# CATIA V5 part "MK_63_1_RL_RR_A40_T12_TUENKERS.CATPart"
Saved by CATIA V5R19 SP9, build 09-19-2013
Part number: MK_63_1_RL_RR_A40_T12_TUENKERS
Material "MISCHDICHTE": density 4951.5 kg/m3, Young's modulus 2e+11 Pa, Poisson ratio 0.266
Bounding box of the stored display mesh (mm): x -193.5 to 132.266, y -121.5 to 144, z -122.161 to 122.161
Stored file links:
  G:\Konstruktion\Modelle\Catia_V5\MK_63_1_RL_RR_A40_T12_TUENKERS.CATPart
  G:\Konstruktion\Modelle\Catia_V5\Spannarme\SPANNARM_KPL_63_A10_217498_TUENKERS.CATPart
  C:\Catia\Tuenkers_B19SP9HF86_64\win_b64\reffiles\standard\MetricThickPitch.txt
  G:\Konstruktion\Modelle\Catia_V5\Spannarme\SPANNARM_KPL_63_A40_242839_TUENKERS.CATPart
  G:\Konstruktion\Modelle\Catia_V5\MK_63_1_A10_T12_TUENKERS.CATPart
  G:\Konstruktion\Modelle\Catia_V5\MK2_63_1_A40_T12_TUENKERS.CATPart
  G:\Konstruktion\Modelle\Catia_V5\V2_63_1_BR3_ZL_ZR_RL_RR_A40_T12_TUENKERS.CATPart
  HANDHEBEL_KPL_50_63_TUENKERS.CATPart
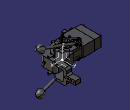
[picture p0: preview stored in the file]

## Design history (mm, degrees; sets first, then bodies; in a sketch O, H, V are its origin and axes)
AxisSystem1: origin (0, 0, 0), X (1, 0, 0), Y (0, 1, 0), Z (0, 0, 1)
Body1 (main body)
  Body2 "*DIT1\\*DIT2\\"
    Solid1: solid without history
  Assemble1: tool Body2
  Body3 "*DIT1\\*DIT3"
    Solid2 "Solid.1": solid without history
  Assemble2: tool Body3
  Body4 "*DIT1\\*DIT12\\*DIT16\\"
    Solid3 "Solid.1": solid without history
  Assemble3: tool Body4
  Body5 "*DIT1\\*DIT12\\*DIT17\\"
    Solid4 "Solid.1": solid without history
  Assemble4: tool Body5
  Body6 "*DIT1\\*DIT12\\MK_MK2_63_1_A10_A11_A12_T12_081112_3D_xSET4_2.1"
    Solid5 "Solid.1": solid without history
    Body7 "*DIT1\\*DIT12\\MK_MK2_63_1_A10_A11_A12_T12_081112_3D_xSET4_2.1\\Body.11 ( *SOL16 - wsp GEHAEUSE -  )"
      Solid6 "Solid.1": solid without history
    Add1 "*DIT1\\*DIT12\\MK_MK2_63_1_A10_A11_A12_T12_081112_3D_xSET4_2.1\\Body.11 ( *SOL16 - wsp GEHAEUSE -  )": tool Body7
    Body8 "*DIT1\\*DIT12\\MK_MK2_63_1_A10_A11_A12_T12_081112_3D_xSET4_2.1\\Body.12 ( *SOL17 - wsp GEHAEUSE -  )"
      Solid7 "Solid.1": solid without history
    Add2 "*DIT1\\*DIT12\\MK_MK2_63_1_A10_A11_A12_T12_081112_3D_xSET4_2.1\\Body.12 ( *SOL17 - wsp GEHAEUSE -  )": tool Body8
    Body9 "*DIT1\\*DIT12\\MK_MK2_63_1_A10_A11_A12_T12_081112_3D_xSET4_2.1\\Body.14 ( *SOL18 - wsp GEHAEUSE -  )"
      Solid8 "Solid.1": solid without history
    Add3 "*DIT1\\*DIT12\\MK_MK2_63_1_A10_A11_A12_T12_081112_3D_xSET4_2.1\\Body.14 ( *SOL18 - wsp GEHAEUSE -  )": tool Body9
  Assemble5: tool Body6
  Body10 "*DIT1\\MK_MK2_63_1_A10_A11_A12_T12_081112_3D_xSET2_1.1"
    Solid9 "Solid.1": solid without history
  Assemble6: tool Body10
  Rotate1: Axis edge [XY plane of AxisSystem1 | ZX plane of AxisSystem1], Angle 90, ToTransfor Assemble6
  Body11
    Body12 "*DIT1\\MK_MK2_63_1_A10_A11_A12_T12_081112_3D_xSET2_1.1\\Body.2 ( *SOL2 - wsp MK_MK2 63_1 -  )"
      Solid10 "Solid.1": solid without history
    Assemble7: tool Body12
    Body13 "*DIT1\\MK_MK2_63_1_A10_A11_A12_T12_081112_3D_xSET2_1.1\\Body.3 ( *SOL3 - wsp MK_MK2 63_1 -  )"
      Solid11 "Solid.1": solid without history
    Assemble8: tool Body13
    Body14 "*DIT1\\MK_MK2_63_1_A10_A11_A12_T12_081112_3D_xSET2_1.1\\Body.4 ( *SOL4 - wsp MK_MK2 63_1 -  )"
      Solid12 "Solid.1": solid without history
    Assemble9: tool Body14
    Body15 "*DIT1\\MK_MK2_63_1_A10_A11_A12_T12_081112_3D_xSET2_1.1\\Body.5 ( *SOL5 - wsp MK_MK2 63_1 -  )"
      Solid13 "Solid.1": solid without history
    Assemble10: tool Body15
    Body16 "*DIT1\\MK_MK2_63_1_A10_A11_A12_T12_081112_3D_xSET2_1.1\\Body.6 ( *SOL6 - wsp MK_MK2 63_1 -  )"
      Solid14 "Solid.1": solid without history
    Assemble11: tool Body16
    Rotate2: Axis edge, Angle 90, ToTransfor Assemble11
    Translate1: Direction edge [YZ plane of AxisSystem1 | XY plane of AxisSystem1], Length -1, ToTransfor Rotate2
  Assemble12: tool Body11
Body17 "Spannarm_kpl_63_A40_242839_Tuenkers", material "Steel"
  Sketch1 on xy-plane, origin (0, 0, 0), H (1, 0, 0), V (0, 1, 0)
    line L1 (73, 144) -> (45, 144)
    arc A1 centre (53, 43.1005) radius 20 from (67.1421, 28.9584) to (73, 43.1005) ccw
    line L2 (67.1421, 28.9584) -> (19.0919, -19.0919)
    line L3 (10.9602, 10.9602) -> (10.9602, -10.9602)
    line L4 (10.9602, 10.9602) -> (-10.9602, 10.9602)
    line L5 (-19.0919, 19.0919) -> (-10.9602, 10.9602)
    line L6 (-1.4396, 36.7442) -> (-19.0919, 19.0919)
    line L7 (38.4202, 51.252) -> (-1.4396, 36.7442)
    arc A2 centre (35, 60.6489) radius 10 from (38.4202, 51.252) to (45, 60.6489) ccw
    line L8 (45, 60.6489) -> (45, 144)
    line L9 (73, 144) -> (73, 43.1005)
    line L10 (10.9602, -10.9602) -> (19.0919, -19.0919)
    point P7 (10.9602, 10.9602)
    point P10 (-1.4396, 36.7442)
    point P13 (73, 37.6447)
    point P14 (45, 51.7188)
    reference intersected line E1 through (0, 0) direction (-0.7071, 0.7071)
    reference intersected line E2 through (0, 0) direction (-0.7071, 0.7071)
    reference intersected line E3 through (0, 0) direction (-0.7071, 0.7071)
    reference intersected line E4 through (0, 0) direction (0, 1) from yz-plane
    reference intersected line E5 through (0, 0) direction (-1, 0) from zx-plane
    reference intersected line E6 through (0, 0) direction (0, 1) from yz-plane
    angle L6 L7 = 25
    radius A1 = 20
    angle L4 L5 = 45
    distance P7 L2 = 27
    distance L2 L6 = 54
    angle L2 L10 = 90
    distance P7 E1 = 15.5
    distance E4 L3 = 10.9602
    distance E5 L1 = 144
    distance E6 L8 = 45
    distance L9 L8 = 28
    radius A2 = 10
    distance P10 L1 = 107.2558
    tangency: A1 L2, L8 A2, A2 L7, L9 A1
    coincidence: L10 E2, L5 E3
  Pad1: profile Sketch1, direction (0, 0, 1), length 39, opposite side length 39
  Chamfer1: length 0.1, angle 45, on edge [face of Pad1 from Sketch1.L3 | end face of Pad1]; edge [face of Pad1 from Sketch1.L4 | end face of Pad1]; edge [start face of Pad1 | face of Pad1 from Sketch1.L4]; edge [start face of Pad1 | face of Pad1 from Sketch1.L3]
  Sketch2 on face of Pad1 from Sketch1.L9, origin (73, 0, 0), H (0, 1, 0), V (0, 0, 1)
    line L1 (144, -10) -> (144, 10)
    line L2 (103, 10) -> (144, 10)
    arc A1 centre (103, 18) radius 8 from (103, 10) to (95, 18) cw
    line L3 (95, 18) -> (95, 29)
    arc A2 centre (85, 29) radius 10 from (85, 39) to (95, 29) cw
    line L4 (-20, 39) -> (85, 39)
    line L5 (-20, 39) -> (-20, 27)
    line L6 (74, 27) -> (-20, 27)
    arc A3 centre (74, 21) radius 6 from (74, 27) to (80, 21) cw
    line L7 (80, 21) -> (80, -21)
    arc A4 centre (74, -21) radius 6 from (80, -21) to (74, -27) cw
    line L8 (-20, -27) -> (74, -27)
    line L9 (-20, -27) -> (-20, -39)
    line L10 (-20, -39) -> (85, -39)
    arc A5 centre (85, -29) radius 10 from (95, -29) to (85, -39) cw
    line L11 (95, -29) -> (95, -18)
    arc A6 centre (103, -18) radius 8 from (95, -18) to (103, -10) cw
    line L12 (103, -10) -> (144, -10)
    reference intersected line E1 through (0, 0) direction (-1, 0) from xy-plane
    reference intersected line E2 through (0, 0) direction (0, 1) from zx-plane
    reference intersected line E3 through (0, 0) direction (0, 1) from zx-plane
    reference intersected line E4 through (0, 0) direction (0, 1) from zx-plane
    line L13 (-30, -44) -> (160, -44)
    line L14 (160, -44) -> (160, 44)
    line L15 (160, 44) -> (-30, 44)
    line L16 (-30, 44) -> (-30, -44)
    reference intersected line E5 through (0, 0) direction (-1, 0) from xy-plane
    reference intersected line E6 through (0, 0) direction (0, 1) from zx-plane
    distance L12 E1 = 10
    distance L12 L2 = 20
    distance L4 L10 = 78
    distance L6 L8 = 54
    distance L10 L12 = 29
    distance L8 L10 = 12
    radius A3 = 6
    radius A4 = 6
    radius A5 = 10
    radius A2 = 10
    radius A1 = 8
    radius A6 = 8
    distance L7 E2 = 80
    distance L3 E3 = 95
    distance L1 L5 = 164
    distance E4 L1 = 144
    distance L16 L14 = 190
    distance L15 L13 = 88
    distance L13 E5 = 44
    distance L14 E6 = 160
    tangency: L6 A3, A3 L7, L7 A4, A4 L8, L10 A5, A5 L11, L3 A1, A1 L2, A6 L12, A2 L4, A2 L3, A6 L11
    vertical: L1 V, L14 V, L16 V
    horizontal: L12 H, L13 H, L15 H
    coincidence: L5 L9, L11 L3
  Pocket1: profile Sketch2, direction (-1, 0, 0), length 95
  Sketch3 on face of Pad1 from Sketch1.L9, origin (73, 131.0889, -0.3784), H (0, 1, 0), V (0, 0, 1)
    point P1 (3.9111, 0.3784)
    reference intersected line E1 through (0, 0.3784) direction (-1, 0) from xy-plane
    reference intersected line E2 through (-131.0889, 0) direction (0, 1) from zx-plane
    reference intersected line E3 through (-131.0889, 0) direction (0, 1) from zx-plane
    reference intersected line E4 (12.9111, -38.6216) -> (-87.9884, -38.6216) from start face of Pad1
    distance P1 E2 = 135
    distance E3 E4 = 0
    coincidence: P1 E1
  Hole1: placed by Sketch3, at (73, 135, 0) direction (-1, 0, 0), diameter 6, through (limit type 6)
  Sketch4 on face of Pad1 from Sketch1.L9, origin (73, 113.9529, 0.5693), H (0, 1, 0), V (0, 0, 1)
    point P1 (-8.9529, -0.5693)
    reference projected point E1 (21.0471, -0.5693) from axis of face of Hole1
    reference intersected line E2 through (0, -0.5693) direction (-1, 0) from xy-plane
    distance P1 E1 = 30
    coincidence: P1 E2
  Hole2: placed by Sketch4, at (73, 105, 0) direction (-1, 0, 0), diameter 6, through (limit type 6)
  Sketch5 on face of Pad1 from Sketch1.L9, origin (73, 123.4122, -0.1089), H (0, 1, 0), V (0, 0, 1)
    point P1 (-3.4122, 0.1089)
    reference projected point E1 (11.5878, 0.1089) from axis of face of Hole1
    reference projected point E2 (-18.4122, 0.1089) from axis of face of Hole2
    distance P1 E1 = 15
    distance E2 P1 = 15
  Hole3: placed by Sketch5, at (73, 120, 0) direction (-1, 0, 0), diameter 9, through (limit type 6)
  Sketch6 on face of Pad1 from Sketch1.L9, origin (73, 93.5248, 1.4062), H (0, 1, 0), V (0, 0, 1)
    point P1 (-3.5248, -1.4062)
    reference projected point E1 (26.4752, -1.4062) from axis of face of Hole3
    reference projected point E2 (11.4752, -1.4062) from axis of face of Hole2
    distance P1 E1 = 30
    distance P1 E2 = 15
  Hole4: placed by Sketch6, at (73, 90, 0) direction (-1, 0, 0), diameter 9, through (limit type 6)
  Sketch7 on face of Pad1 from Sketch1.L10, origin (13.7879, -13.7879, 28.7565), H (0.7071, -0.7071, 0), V (0, 0, 1)
    point P1 (0.5009, 4.2435)
    reference intersected line E1 through (0, -28.7565) direction (-1, 0) from xy-plane
    reference projected line E2 (-19.4991, -67.7565) -> (-19.4991, 10.2435) from edge [face of Pad1 from Sketch1.L3 | face of Pad1 from Sketch1.L4]
    distance P1 E1 = 33
    distance E2 P1 = 20
  Hole5: placed by Sketch7, at (14.1421, -14.1421, 33) direction (0.7071, 0.7071, 0), diameter 6.647, depth 18, V-bottom angle 120, threaded "M8", thread diameter 8, thread depth 15, pitch 1.25
  RectPattern1: of Hole5, direction 1 instances 2, spacing 66, along edge [face of Pad1 from Sketch1.L3 | face of Pad1 from Sketch1.L4] reversed, direction 2 instances 2, spacing 40, along edge [face of Pad1 from Sketch1.L10 | face of Pocket1] reversed
  Body18 "KLEMMFLANSCH KPL"
    Sketch8 on xy-plane, origin (0, 0, 0), H (1, 0, 0), V (0, 1, 0)
      line L1 (-20.5061, 17.6777) -> (-31.1375, 7.0463)
      line L2 (-31.1375, 7.0463) -> (-19.1167, -4.9745)
      line L3 (-19.1167, -4.9745) -> (-25.4806, -11.3385)
      line L4 (-25.4806, -11.3385) -> (-11.3385, -25.4806)
      line L5 (-11.3385, -25.4806) -> (-4.9745, -19.1167)
      line L6 (-4.9745, -19.1167) -> (7.0463, -31.1375)
      line L7 (7.0463, -31.1375) -> (19.0671, -19.1167)
      line L8 (19.0671, -19.1167) -> (10.9106, -10.9602)
      line L9 (10.9106, -10.9602) -> (-10.9602, -10.9602)
      point P10 (-10.9602, -10.9602)
      line L10 (-10.9602, -10.9602) -> (-10.9602, 8.1317)
      line L11 (-10.9602, 8.1317) -> (-20.5061, 17.6777)
      reference intersected line E1 through (0, 0) direction (-0.7071, 0.7071)
      reference intersected line E2 through (0, 0) direction (-0.7071, 0.7071)
      reference intersected line E3 through (0, 0) direction (-0.7071, -0.7071)
      distance L4 L8 = 26
      distance L7 L5 = 17
      distance L5 L3 = 20
      distance L7 L1 = 54
      distance L4 L6 = 9
      distance E1 P10 = 15.5
      distance L11 E2 = 2
      distance L11 L8 = 1.965
      angle L11 L10 = 135
      angle L9 L8 = 45
      distance L7 P10 = 27
      distance E3 L7 = 27
      coincidence: L2 L6
    Pad2: profile Sketch8, direction (0, 0, 1), length 39, opposite side length -27
    Chamfer2: length 0.1, angle 45, on edge [face of Pad2 from Sketch8.L9 | end face of Pad2]; edge [face of Pad2 from Sketch8.L10 | end face of Pad2]
    Sketch9 on face of Pad2 from Sketch8.L6, origin (-12.0456, -12.0456, 0), H (0.7071, -0.7071, 0), V (0, 0, 1)
      circle A1 centre (20, 33) radius 4
      point P1 (20, 33)
      circle A2 centre (-20, 33) radius 4
      point P2 (-20, 33)
      reference projected line E1 (-27, 27) -> (-10, 27) from edge [start face of Pad2 | face of Pad2 from Sketch8.L2]
      reference projected line E2 (10, 27) -> (27, 27) from edge [start face of Pad2 | face of Pad2 from Sketch8.L6]
      reference projected line E3 (27, 27) -> (27, 39) from edge [face of Pad2 from Sketch8.L7 | face of Pad2 from Sketch8.L6]
      reference projected line E4 (-27, 27) -> (-27, 39) from edge [face of Pad2 from Sketch8.L2 | face of Pad2 from Sketch8.L1]
      radius A1 = 4
      radius A2 = 4
      distance E1 P2 = 6
      distance P1 E2 = 6
      distance E3 P1 = 7
      distance P2 E4 = 7
    Pad3: profile Sketch9, direction (0.7071, 0.7071, 0), length 20
    Sketch10 on face of Pad3, origin (-12.0456, -12.0456, 0), H (0.7071, -0.7071, 0), V (0, 0, 1)
      circle A1 centre (20, 33) radius 6.5
      point P1 (20, 33)
      circle A2 centre (-20, 33) radius 6.5
      point P2 (-20, 33)
      reference projected line E1 (-27, 27) -> (-27, 39) from edge [face of Pad2 from Sketch8.L2 | face of Pad2 from Sketch8.L1]
      reference projected line E2 (27, 27) -> (27, 39) from edge [face of Pad2 from Sketch8.L7 | face of Pad2 from Sketch8.L6]
      reference projected line E3 (-27, 27) -> (-10, 27) from edge [start face of Pad2 | face of Pad2 from Sketch8.L2]
      reference projected line E4 (10, 27) -> (27, 27) from edge [start face of Pad2 | face of Pad2 from Sketch8.L6]
      radius A1 = 6.5
      radius A2 = 6.5
      distance E1 P2 = 7
      distance E2 P1 = 7
      distance E3 P2 = 6
      distance E4 P1 = 6
    Pad4: profile Sketch10, direction (-0.7071, -0.7071, 0), length 1.4
    Chamfer3: length 0.1, angle 45, on edge [face of Pad4 from Sketch10.A1 | end face of Pad4]; edge [face of Pad4 from Sketch10.A2 | end face of Pad4]
    Sketch11 on end face of Pad4, origin (-13.0355, -13.0355, 0), H (0.7071, -0.7071, 0), V (0, 0, 1)
      circle A1 centre (20, 33) radius 6.5
      point P1 (20, 33)
      circle A2 centre (-20, 33) radius 6.5
      point P2 (-20, 33)
      reference projected line E1 (10, 27) -> (27, 27) from edge [start face of Pad2 | face of Pad3]
      reference projected line E2 (27, 27) -> (27, 39) from edge [face of Pad2 from Sketch8.L7 | face of Pad2 from Sketch8.L6]
      reference projected line E3 (-27, 27) -> (-27, 39) from edge [face of Pad2 from Sketch8.L2 | face of Pad2 from Sketch8.L1]
      reference projected line E4 (-27, 27) -> (-10, 27) from edge [start face of Pad2 | face of Pad3]
      radius A1 = 6.5
      radius A2 = 6.5
      distance E1 P1 = 6
      distance E2 P1 = 7
      distance E3 P2 = 7
      distance E4 P2 = 6
    Pad5: profile Sketch11, direction (-0.7071, -0.7071, 0), length 8
    Fillet1: radius 0.5, on end face of Pad5; edge [face of Pad5 from Sketch11.A1 | end face of Pad5]
    Mirror1: of the body so far, about xy-plane, deactivated
  Assemble13: tool Body18
Body19 "ENDLAGENRASTE_RECHTS"
  Body20 "LUMP69"
    Solid15 "Manifold Solid #2521": solid without history
  Assemble14: tool Body20
  Body21 "LUMP71"
    Solid16 "Manifold Solid #3035": solid without history
  Assemble15: tool Body21
  Body22 "LUMP72"
    Solid17 "Manifold Solid #3745": solid without history
  Assemble16: tool Body22
  Body23 "LUMP75"
    Solid18 "Manifold Solid #6741": solid without history
  Assemble17: tool Body23
  Body24 "LUMP77"
    Solid19 "Manifold Solid #7511": solid without history
  Assemble18: tool Body24
  Body25 "LUMP78"
    Solid20 "Manifold Solid #7920": solid without history
  Assemble19: tool Body25
  Body26 "LUMP80"
    Solid21 "Manifold Solid #8586": solid without history
  Assemble20: tool Body26
  Body27 "LUMP83"
    Solid22 "Manifold Solid #9661": solid without history
  Assemble21: tool Body27
  Body28 "LUMP84"
    Solid23 "Manifold Solid #9918": solid without history
  Assemble22: tool Body28
  Body29 "LUMP86"
    Solid24 "Manifold Solid #10584": solid without history
  Assemble23: tool Body29
  Body30 "LUMP90"
    Solid25 "Manifold Solid #12531": solid without history
  Assemble24: tool Body30
  Body31 "LUMP91"
    Solid26 "Manifold Solid #13299": solid without history
  Assemble25: tool Body31
  Body32 "LUMP92"
    Solid27 "Manifold Solid #13708": solid without history
  Assemble26: tool Body32
  Body33 "LUMP95"
    Solid28 "Manifold Solid #14479": solid without history
    Translate2: Direction edge [face of Solid26 | face of Solid26], Length -4, ToTransfor Solid28
  Assemble27: tool Body33
  Body34 "LUMP96"
    Solid29 "Manifold Solid #14736": solid without history
    Translate3: Direction edge [face of Solid26 | face of Solid26], Length -4, ToTransfor Solid29
  Assemble28: tool Body34
  Body35 "LUMP99"
    Solid30 "Manifold Solid #15963": solid without history
    Translate4: Direction edge [face of Solid26 | face of Solid26], Length -4, ToTransfor Solid30
  Assemble29: tool Body35
  Body36 "LUMP100"
    Solid31 "Manifold Solid #16372": solid without history
    Translate5: Direction edge [face of Solid26 | face of Solid26], Length -4, ToTransfor Solid31
  Assemble30: tool Body36
  Body37 "LUMP103"
    Solid32 "Manifold Solid #17295": solid without history
  Assemble31: tool Body37
  Rotate3: Axis edge, Angle 90, ToTransfor Assemble31
Body38 "ENDLAGENRASTE_LINKS"
  Solid33 "Manifold Solid #1213": solid without history
  Body39 "LUMP70"
    Solid34 "Manifold Solid #2778": solid without history
  Assemble32: tool Body39
  Body40 "LUMP73"
    Solid35 "Manifold Solid #4455": solid without history
  Assemble33: tool Body40
  Body41 "LUMP74"
    Solid36 "Manifold Solid #5598": solid without history
  Assemble34: tool Body41
  Body42 "LUMP76"
    Solid37 "Manifold Solid #7126": solid without history
  Assemble35: tool Body42
  Body43 "LUMP79"
    Solid38 "Manifold Solid #8329": solid without history
  Assemble36: tool Body43
  Body44 "LUMP81"
    Solid39 "Manifold Solid #8843": solid without history
  Assemble37: tool Body44
  Body45 "LUMP82"
    Solid40 "Manifold Solid #9252": solid without history
  Assemble38: tool Body45
  Body46 "LUMP85"
    Solid41 "Manifold Solid #10175": solid without history
  Assemble39: tool Body46
  Body47 "LUMP87"
    Solid42 "Manifold Solid #10993": solid without history
  Assemble40: tool Body47
  Body48 "LUMP88"
    Solid43 "Manifold Solid #11378": solid without history
  Assemble41: tool Body48
  Body49 "LUMP89"
    Solid44 "Manifold Solid #12146": solid without history
  Assemble42: tool Body49, deactivated
  Body50 "LUMP93"
    Solid45 "Manifold Solid #13965": solid without history
  Assemble43: tool Body50, deactivated
  Body51 "LUMP94"
    Solid46 "Manifold Solid #14222": solid without history
  Assemble44: tool Body51, deactivated
  Body52 "LUMP97"
    Solid47 "Manifold Solid #15145": solid without history
  Assemble45: tool Body52, deactivated
  Body53 "LUMP98"
    Solid48 "Manifold Solid #15554": solid without history
  Assemble46: tool Body53, deactivated
  Body54 "LUMP101"
    Solid49 "Manifold Solid #16781": solid without history
  Assemble47: tool Body54
  Body55 "LUMP102"
    Solid50 "Manifold Solid #17038": solid without history
  Assemble48: tool Body55
  Rotate4: Axis edge, Angle 90, ToTransfor Assemble48
Body56 "Handhebel_KPL_218625_TUENKERS.1"
  Solid51: solid without history
  Body57 "Handhebel_KPL_218625_TUENKERS.2"
    Solid52: solid without history
  Assemble49: tool Body57
  Translate6: Direction edge [ZX plane of AxisSystem1 | YZ plane of AxisSystem1], ToTransfor Assemble49, Length 28
  Translate7: Direction edge [XY plane of AxisSystem1 | ZX plane of AxisSystem1], ToTransfor Translate6, Length -86
  Translate8: Direction edge [YZ plane of AxisSystem1 | XY plane of AxisSystem1], ToTransfor Translate7, Length -4
Body58 "Handhebel_KPL_218625_TUENKERS.1"
  Solid53: solid without history
  Body59 "Handhebel_KPL_218625_TUENKERS.2"
    Solid54: solid without history
  Assemble50: tool Body59
  Translate9: Direction edge [ZX plane of AxisSystem1 | YZ plane of AxisSystem1], Length 28, ToTransfor Assemble50
  Translate10: Direction edge [XY plane of AxisSystem1 | ZX plane of AxisSystem1], Length -86, ToTransfor Translate9
  Translate11: Direction edge [YZ plane of AxisSystem1 | XY plane of AxisSystem1], Length -4, ToTransfor Translate10
  Symmetry1: ToTransfor Translate11, Reference XY plane of AxisSystem1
